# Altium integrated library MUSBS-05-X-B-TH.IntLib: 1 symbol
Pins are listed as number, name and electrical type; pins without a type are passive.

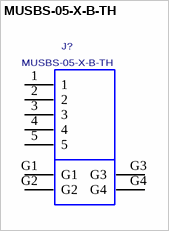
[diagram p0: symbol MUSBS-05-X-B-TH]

## MUSBS-05-X-B-TH
designator J?
MUSB TYPE B, VERTICAL SEALED.; MANUDACTURER: SAMTEC
footprint MUSBS-05-X-B-TH
pins: 1, 2, 3, 4, 5, G1, G2, G3, G4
